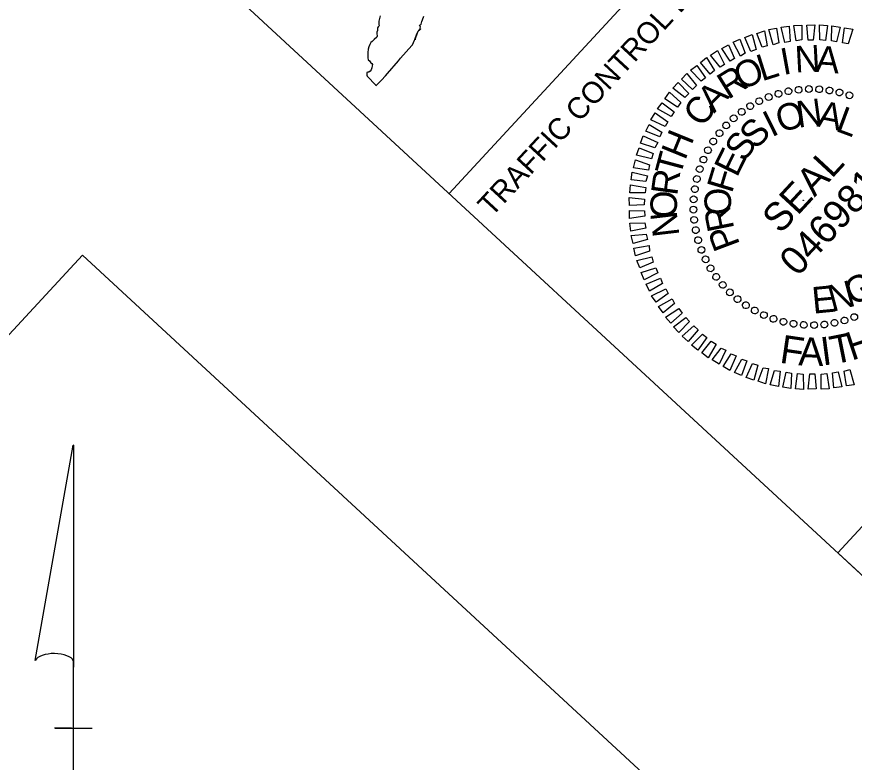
# Model space of a CAD drawing. Extents: x 1768064 to 1770025, y 999327 to 1001342.
# Drawn here: x 1769141.4 to 1769319.3, y 1000999.4 to 1001157.8 of the extents above; entities that cross this region are included whole.
import ezdxf

# ---------------------------------------------------------------- set-up
doc = ezdxf.new("R2010")
doc.units = 0
for name, color, linetype in [('E_NCDOT_Terrain_Model_Contour_Imported', 7, 'Continuous'), ('E_NCDOT_Terrain_Model_Spot_Elevation', 7, 'Continuous'), ('E_NCDOT_Terrain_Model_Void', 7, 'Continuous'), ('P_NCDOT_Horizontal_Alignment_Direction_Label', 7, 'Continuous'), ('P_NCDOT_Horizontal_Alignment_Station_Major_Label', 7, 'Continuous'), ('P_NCDOT_Horizontal_Alignment_Tick_Large', 7, 'Continuous'), ('P_NCDOT_Horizontal_Alignment_Tick_Small', 7, 'Continuous')]:
    doc.layers.add(name, color=color, linetype=linetype)

msp = doc.modelspace()

# ---------------------------------------------------------------- linework, layer by layer
at = {"layer": 'E_NCDOT_Terrain_Model_Contour_Imported'}
for p, q in [((1769301.12, 1001193.68), (1769233.28, 1001120.29)), ((1769301.12, 1001193.68), (1769233.28, 1001120.29)), ((1769315.85, 1001043.97), (1769315.85, 1001043.97))]:
    msp.add_line(p, q, dxfattribs=at)
msp.add_circle((1769308.49, 1001118.82), 0.06, dxfattribs=at)
at = {"layer": 'E_NCDOT_Terrain_Model_Spot_Elevation'}
msp.add_line((1769904.54, 1000499.71), (1769151.86, 1001195.48), dxfattribs=at)
at = {"layer": 'E_NCDOT_Terrain_Model_Void'}
for points in [[(1769218.62, 1001158.06), (1769218.45, 1001157.49), (1769218.3, 1001156.86), (1769218.32, 1001156.44), (1769218.35, 1001156.15), (1769218.36, 1001155.91), (1769218.18, 1001155.67), (1769218.03, 1001155.47), (1769218.04, 1001155.18), (1769218.05, 1001154.88), (1769217.91, 1001154.56), (1769217.88, 1001154.27), (1769217.96, 1001153.74), (1769217.87, 1001153.49), (1769217.32, 1001152.97), (1769216.87, 1001152.58), (1769216.65, 1001152.36), (1769216.42, 1001151.94), (1769216.22, 1001151.43), (1769216.06, 1001150.93), (1769216, 1001150.24), (1769215.98, 1001149.58), (1769215.96, 1001149.13), (1769216.04, 1001148.71), (1769216.31, 1001148.48), (1769216.5, 1001148.27), (1769216.59, 1001148.01), (1769216.85, 1001147.88), (1769216.94, 1001147.7), (1769216.87, 1001147.41), (1769216.82, 1001146.97), (1769216.71, 1001146.58), (1769216.48, 1001146.24), (1769216.23, 1001146.05), (1769215.99, 1001146.08), (1769215.77, 1001145.96), (1769215.74, 1001145.42), (1769215.86, 1001145.2), (1769217.68, 1001143.27), (1769217.69, 1001143.17), (1769218.88, 1001144.36), (1769219.73, 1001145.31), (1769220.17, 1001145.8), (1769222.49, 1001148.5), (1769222.9, 1001149), (1769225.3, 1001151.75), (1769225.49, 1001151.88), (1769225.93, 1001152.86), (1769225.97, 1001153.02), (1769226.4, 1001154.21), (1769226.67, 1001154.77), (1769226.79, 1001154.94), (1769226.98, 1001154.96), (1769227.05, 1001155.15), (1769227.16, 1001155.67), (1769227.06, 1001155.83), (1769226.96, 1001155.97), (1769227.11, 1001156.1), (1769227.29, 1001156.27), (1769227.48, 1001156.79), (1769227.82, 1001157.72), (1769227.88, 1001157.97)], [(1769227.15, 1001155.27), (1769227.07, 1001155.08), (1769226.88, 1001155.06), (1769226.76, 1001154.89), (1769226.49, 1001154.32), (1769226.05, 1001153.12), (1769226.01, 1001152.96)]]:
    msp.add_lwpolyline(points, dxfattribs=at)
at = {"layer": 'P_NCDOT_Horizontal_Alignment_Direction_Label'}
for p, q in [((1769145.3, 1001021.09), (1769153.39, 1001066.8)), ((1769153.44, 1001066.8), (1769153.39, 1001066.8)), ((1769153.44, 1001066.8), (1769153.39, 1001066.8)), ((1769153.44, 1001066.8), (1769153.43, 1001019.66)), ((1769153.43, 1000995.21), (1769153.43, 1001021.04)), ((1769153.43, 1001019.66), (1769153.43, 1001021)), ((1769149.49, 1001006.65), (1769149.44, 1001006.65)), ((1769152.99, 1001006.65), (1769149.49, 1001006.65)), ((1769149.54, 1001006.65), (1769157.42, 1001006.65))]:
    msp.add_line(p, q, dxfattribs=at)
msp.add_ellipse((1769149.38, 1001020.61), major_axis=(4.17, -0.03), ratio=0.461098, start_param=0.216388, end_param=2.908219, dxfattribs=at)
at = {"layer": 'P_NCDOT_Horizontal_Alignment_Station_Major_Label'}
msp.add_lwpolyline([(1769315.85, 1001043.97), (1769383.69, 1001117.36), (1769393.04, 1001108.72), (1769325.2, 1001035.33)], close=True, dxfattribs=at)
at = {"layer": 'P_NCDOT_Horizontal_Alignment_Tick_Large'}
for p, q in [((1769305.34, 1001142.01), (1769305.34, 1001142.01)), ((1769307.52, 1001142.37), (1769307.52, 1001142.37)), ((1769309.68, 1001142.49), (1769309.68, 1001142.49)), ((1769311.91, 1001142.48), (1769311.91, 1001142.48)), ((1769314.04, 1001142.21), (1769314.04, 1001142.21)), ((1769301.15, 1001140.78), (1769301.15, 1001140.78)), ((1769303.2, 1001141.53), (1769303.2, 1001141.53)), ((1769316.22, 1001141.76), (1769316.22, 1001141.76)), ((1769318.33, 1001141.17), (1769318.33, 1001141.17)), ((1769297.19, 1001138.85), (1769297.19, 1001138.85)), ((1769299.13, 1001139.92), (1769299.13, 1001139.92)), ((1769295.43, 1001137.62), (1769295.43, 1001137.62)), ((1769293.71, 1001136.28), (1769293.71, 1001136.28)), ((1769290.65, 1001133.11), (1769290.65, 1001133.11)), ((1769292.11, 1001134.76), (1769292.11, 1001134.76)), ((1769289.42, 1001131.33), (1769289.42, 1001131.33)), ((1769288.22, 1001129.44), (1769288.22, 1001129.44)), ((1769287.23, 1001127.49), (1769287.23, 1001127.49)), ((1769286.46, 1001125.48), (1769286.46, 1001125.48)), ((1769285.87, 1001123.37), (1769285.87, 1001123.37)), ((1769285.43, 1001121.2), (1769285.43, 1001121.2)), ((1769285.16, 1001119.06), (1769285.16, 1001119.06)), ((1769310.24, 1001117.39), (1769310.24, 1001117.39)), ((1769285.14, 1001116.83), (1769285.14, 1001116.83)), ((1769285.26, 1001114.68), (1769285.26, 1001114.68)), ((1769285.63, 1001112.5), (1769285.63, 1001112.5)), ((1769286.1, 1001110.36), (1769286.1, 1001110.36)), ((1769286.85, 1001108.3), (1769286.85, 1001108.3)), ((1769287.71, 1001106.28), (1769287.71, 1001106.28)), ((1769288.78, 1001104.34), (1769288.78, 1001104.34)), ((1769290.01, 1001102.59), (1769290.01, 1001102.59)), ((1769291.36, 1001100.87), (1769291.36, 1001100.87)), ((1769292.87, 1001099.27), (1769292.87, 1001099.27)), ((1769294.52, 1001097.81), (1769294.52, 1001097.81)), ((1769296.3, 1001096.57), (1769296.3, 1001096.57)), ((1769298.19, 1001095.37), (1769298.19, 1001095.37)), ((1769300.14, 1001094.39), (1769300.14, 1001094.39)), ((1769302.15, 1001093.62), (1769302.15, 1001093.62)), ((1769304.26, 1001093.03), (1769304.26, 1001093.03)), ((1769306.44, 1001092.58), (1769306.44, 1001092.58)), ((1769308.57, 1001092.31), (1769308.57, 1001092.31)), ((1769310.8, 1001092.29), (1769310.8, 1001092.29)), ((1769312.95, 1001092.41), (1769312.95, 1001092.41)), ((1769315.13, 1001092.78), (1769315.13, 1001092.78)), ((1769317.27, 1001093.26), (1769317.27, 1001093.26))]:
    msp.add_line(p, q, dxfattribs=at)
for points in [[(1769299.77, 1001151.37), (1769298.6, 1001154.3), (1769300.24, 1001154.83), (1769300.86, 1001151.67)], [(1769302.09, 1001151.89), (1769301.15, 1001155.14), (1769302.8, 1001155.39), (1769303.28, 1001152.29)], [(1769304.58, 1001152.38), (1769303.82, 1001155.6), (1769305.51, 1001155.81), (1769305.74, 1001152.6)], [(1769307.01, 1001152.72), (1769306.49, 1001155.99), (1769308.19, 1001156.06), (1769308.2, 1001152.91)], [(1769309.52, 1001152.85), (1769309.25, 1001156.03), (1769310.95, 1001156.1), (1769310.61, 1001152.86)], [(1769312.03, 1001152.92), (1769311.93, 1001156.13), (1769313.64, 1001155.99), (1769313.24, 1001152.75)], [(1769314.48, 1001152.7), (1769314.6, 1001155.92), (1769316.31, 1001155.63), (1769315.58, 1001152.49)], [(1769316.86, 1001152.26), (1769317.27, 1001155.49), (1769319.01, 1001155.17), (1769318.07, 1001152.09)], [(1769295.14, 1001149.46), (1769293.61, 1001152.44), (1769295, 1001153.06), (1769296.18, 1001150.07)], [(1769297.37, 1001150.47), (1769296.05, 1001153.39), (1769297.62, 1001154.05), (1769298.52, 1001150.9)], [(1769292.95, 1001148.42), (1769291.19, 1001151.07), (1769292.61, 1001151.87), (1769293.92, 1001148.95)], [(1769288.71, 1001145.6), (1769286.67, 1001148.1), (1769287.97, 1001149.14), (1769289.64, 1001146.38)], [(1769290.85, 1001147.1), (1769288.8, 1001149.67), (1769290.25, 1001150.65), (1769291.74, 1001147.7)], [(1769286.79, 1001144.11), (1769284.54, 1001146.46), (1769285.88, 1001147.47), (1769287.75, 1001144.85)], [(1769284.98, 1001142.37), (1769282.6, 1001144.58), (1769283.75, 1001145.76), (1769285.83, 1001143.22)], [(1769283.32, 1001140.64), (1769280.76, 1001142.67), (1769281.92, 1001143.84), (1769284.17, 1001141.49)], [(1769281.8, 1001138.64), (1769279.08, 1001140.41), (1769280.09, 1001141.79), (1769282.51, 1001139.62)], [(1769280.4, 1001136.67), (1769277.5, 1001138.26), (1769278.51, 1001139.57), (1769281.1, 1001137.66)], [(1769279.17, 1001134.54), (1769276.14, 1001135.9), (1769277.04, 1001137.39), (1769279.7, 1001135.48)], [(1769278.02, 1001132.33), (1769275.03, 1001133.52), (1769275.76, 1001134.97), (1769278.47, 1001133.34)], [(1769276.94, 1001129.99), (1769273.93, 1001131), (1769274.51, 1001132.51), (1769277.57, 1001131.11)], [(1769276.22, 1001127.66), (1769273.08, 1001128.39), (1769273.62, 1001130), (1769276.64, 1001128.78)], [(1769275.64, 1001125.27), (1769272.4, 1001125.74), (1769272.87, 1001127.42), (1769275.85, 1001126.37)], [(1769275.07, 1001122.81), (1769271.94, 1001123.18), (1769272.12, 1001124.78), (1769275.37, 1001124.02)], [(1769274.88, 1001120.39), (1769271.66, 1001120.44), (1769271.8, 1001122.15), (1769275.05, 1001121.53)], [(1769274.66, 1001117.87), (1769271.55, 1001117.75), (1769271.48, 1001119.44), (1769274.79, 1001119.04)], [(1769274.82, 1001115.47), (1769271.59, 1001114.99), (1769271.59, 1001116.69), (1769274.78, 1001116.6)], [(1769275.03, 1001112.9), (1769271.84, 1001112.31), (1769271.63, 1001114), (1769274.85, 1001114.02)], [(1769275.41, 1001110.51), (1769272.33, 1001109.68), (1769271.91, 1001111.36), (1769275.15, 1001111.63)], [(1769275.86, 1001108.05), (1769272.86, 1001107.01), (1769272.51, 1001108.69), (1769275.74, 1001109.24)], [(1769276.62, 1001105.71), (1769273.77, 1001104.46), (1769273.14, 1001106.06), (1769276.33, 1001106.79)], [(1769277.63, 1001103.41), (1769274.69, 1001101.91), (1769274.06, 1001103.52), (1769277.17, 1001104.52)], [(1769278.57, 1001101.18), (1769275.81, 1001099.52), (1769275.11, 1001101.05), (1769278.17, 1001102.3)], [(1769279.82, 1001099), (1769277.24, 1001097.17), (1769276.27, 1001098.54), (1769279.32, 1001100.01)], [(1769281.15, 1001096.9), (1769278.75, 1001094.89), (1769277.74, 1001096.3), (1769280.65, 1001097.9)], [(1769282.75, 1001094.87), (1769280.35, 1001092.73), (1769279.24, 1001094.03), (1769282.03, 1001095.87)], [(1769284.34, 1001093.06), (1769282.06, 1001090.74), (1769280.92, 1001091.93), (1769283.53, 1001093.95)], [(1769286.14, 1001091.33), (1769284.05, 1001088.84), (1769282.8, 1001089.99), (1769285.26, 1001092.14)], [(1769288.01, 1001089.67), (1769286.1, 1001087.01), (1769284.78, 1001088.09), (1769287.06, 1001090.41)], [(1769289.98, 1001088.26), (1769288.28, 1001085.39), (1769286.93, 1001086.44), (1769288.96, 1001088.92)], [(1769292.04, 1001086.96), (1769290.6, 1001084), (1769289.15, 1001084.93), (1769291.07, 1001087.45)], [(1769294.21, 1001085.77), (1769292.89, 1001082.64), (1769291.47, 1001083.54), (1769293.21, 1001086.22)], [(1769296.52, 1001084.73), (1769295.4, 1001081.61), (1769293.89, 1001082.25), (1769295.41, 1001085.07)], [(1769298.86, 1001083.79), (1769297.96, 1001080.61), (1769296.34, 1001081.22), (1769297.71, 1001084.17)], [(1769301.11, 1001083.07), (1769300.5, 1001079.82), (1769298.92, 1001080.4), (1769300.01, 1001083.27)], [(1769303.61, 1001082.53), (1769303.21, 1001079.29), (1769301.46, 1001079.61), (1769302.4, 1001082.69)], [(1769306, 1001082.09), (1769305.88, 1001078.87), (1769304.17, 1001079.15), (1769304.89, 1001082.3)], [(1769308.45, 1001081.87), (1769308.54, 1001078.65), (1769306.84, 1001078.8), (1769307.24, 1001082.04)], [(1769310.96, 1001081.93), (1769311.23, 1001078.76), (1769309.53, 1001078.69), (1769309.86, 1001081.93)], [(1769313.47, 1001082.07), (1769313.98, 1001078.8), (1769312.29, 1001078.73), (1769312.27, 1001081.88)], [(1769315.89, 1001082.41), (1769316.66, 1001079.19), (1769314.97, 1001078.98), (1769314.74, 1001082.19)], [(1769318.39, 1001082.9), (1769319.33, 1001079.64), (1769317.68, 1001079.4), (1769317.2, 1001082.5)]]:
    msp.add_lwpolyline(points, close=True, dxfattribs=at)
for centre, major_axis in [((1769303.22, 1001141.47), (-0.201, 0.691)), ((1769305.34, 1001141.99), (-0.14, 0.706)), ((1769307.51, 1001142.33), (-0.078, 0.716)), ((1769309.69, 1001142.47), (-0.016, 0.72)), ((1769311.88, 1001142.42), (0.047, 0.718)), ((1769314.05, 1001142.18), (0.11, 0.712)), ((1769316.2, 1001141.76), (0.171, 0.699)), ((1769318.3, 1001141.14), (0.231, 0.682)), ((1769299.14, 1001139.89), (-0.318, 0.646)), ((1769301.15, 1001140.77), (-0.261, 0.671)), ((1769295.41, 1001137.62), (-0.426, 0.581)), ((1769297.23, 1001138.84), (-0.374, 0.616)), ((1769293.7, 1001136.25), (-0.475, 0.541)), ((1769292.12, 1001134.74), (-0.52, 0.498)), ((1769290.68, 1001133.09), (-0.562, 0.451)), ((1769289.38, 1001131.33), (-0.599, 0.4)), ((1769288.25, 1001129.46), (-0.631, 0.346)), ((1769287.28, 1001127.49), (-0.659, 0.29)), ((1769286.49, 1001125.46), (-0.682, 0.231)), ((1769285.88, 1001123.36), (-0.699, 0.171)), ((1769285.45, 1001121.21), (-0.712, 0.11)), ((1769285.21, 1001119.03), (-0.718, 0.047)), ((1769285.16, 1001116.85), (-0.72, -0.016)), ((1769285.31, 1001114.66), (-0.716, -0.078)), ((1769285.64, 1001112.5), (-0.706, -0.14)), ((1769286.16, 1001110.38), (-0.691, -0.201)), ((1769286.86, 1001108.3), (-0.671, -0.261)), ((1769287.74, 1001106.3), (-0.646, -0.318)), ((1769288.8, 1001104.38), (-0.616, -0.374)), ((1769290.01, 1001102.56), (-0.581, -0.426)), ((1769291.38, 1001100.86), (-0.541, -0.475)), ((1769292.9, 1001099.28), (-0.498, -0.52)), ((1769294.54, 1001097.83), (-0.451, -0.562)), ((1769296.3, 1001096.54), (-0.4, -0.599)), ((1769298.18, 1001095.41), (-0.346, -0.631)), ((1769300.14, 1001094.44), (-0.29, -0.659)), ((1769302.18, 1001093.65), (-0.231, -0.682)), ((1769317.26, 1001093.32), (0.201, -0.691)), ((1769319.33, 1001094.02), (0.261, -0.671)), ((1769304.28, 1001093.03), (-0.171, -0.699)), ((1769306.42, 1001092.61), (-0.11, -0.712)), ((1769308.6, 1001092.37), (-0.047, -0.718)), ((1769310.79, 1001092.32), (0.016, -0.72)), ((1769312.97, 1001092.46), (0.078, -0.716)), ((1769315.13, 1001092.8), (0.14, -0.706))]:
    msp.add_ellipse(centre, major_axis=major_axis, ratio=0.999708, dxfattribs=at)
at = {"layer": 'P_NCDOT_Horizontal_Alignment_Tick_Small'}
msp.add_lwpolyline([(1768865.94, 999468.18), (1769816.23, 1000496.25), (1769155.33, 1001107.16), (1768205.03, 1000079.09)], close=True, dxfattribs=at)

# ---------------------------------------------------------------- texts
at = {"layer": 'E_NCDOT_Terrain_Model_Contour_Imported'}
msp.add_text('TRAFFIC CONTROL ENGINEER', height=4.5573, rotation=47.2512, dxfattribs=at).set_placement((1769242.29, 1001115.13))
at = {"layer": 'P_NCDOT_Horizontal_Alignment_Tick_Large'}
for s, height, rotation, p in [('I', 5.64, 10.2714, (1769304.22, 1001145.43)), ('N', 5.64, 3.0701, (1769306.82, 1001145.96)), ('A', 5.64, 355.8684, (1769310.98, 1001146.12)), ('L', 5.64, 17.4721, (1769299.71, 1001144.08)), ('O', 5.64, 24.6724, (1769295.36, 1001142.11)), ('R', 5.64, 31.8723, (1769292.54, 1001140.16)), ('A', 5.64, 46.2715, (1769289.54, 1001137.21)), ('C', 5.64, 53.4711, (1769287.08, 1001134.1)), ('N', 5.64, 7.7278, (1769307.42, 1001134.23)), ('O', 5.64, 17.0847, (1769303.68, 1001133.13)), ('A', 5.64, 349.0115, (1769311.26, 1001134.56)), ('L', 5.64, 339.6521, (1769315.12, 1001133.65)), ('I', 5.64, 26.4408, (1769301.8, 1001132.14)), ('S', 5.64, 45.1516, (1769298.37, 1001129.45)), ('H', 5.64, 67.8707, (1769283.39, 1001127.17)), ('S', 5.64, 54.5068, (1769295.96, 1001126.78)), ('E', 5.64, 63.8623, (1769294.39, 1001123.53)), ('T', 5.64, 75.071, (1769282.39, 1001123.66)), ('SEAL', 5.998, 47.2512, (1769303.64, 1001111.51)), ('R', 5.64, 82.2717, (1769281.7, 1001119.67)), ('F', 5.64, 73.2183, (1769293.32, 1001120.16)), ('046981', 5.998, 47.2512, (1769307.31, 1001102.43)), ('O', 5.64, 91.9325, (1769293.25, 1001115.74)), ('O', 5.64, 89.473, (1769281.64, 1001115.03)), ('R', 5.64, 101.2909, (1769293.86, 1001112.79)), ('N', 5.64, 96.6747, (1769282.2, 1001111.37)), ('P', 5.64, 110.6501, (1769295.12, 1001109.44)), ('G', 5.64, 24.2415, (1769318.85, 1001096.36)), ('N', 5.64, 14.8852, (1769314.62, 1001095.1)), ('E', 5.64, 5.5281, (1769310.6, 1001094.73)), ('T', 6, 11.3243, (1769314.83, 1001083.94)), ('H', 6, 18.1246, (1769318.76, 1001084.72)), ('F', 6, 351.6655, (1769303.31, 1001084.35)), ('A', 6, 358.6821, (1769307.4, 1001083.75)), ('I', 6, 7.5224, (1769312.6, 1001083.71))]:
    msp.add_text(s, height=height, rotation=rotation, dxfattribs=at).set_placement(p)

doc.saveas('drawing.dxf')
